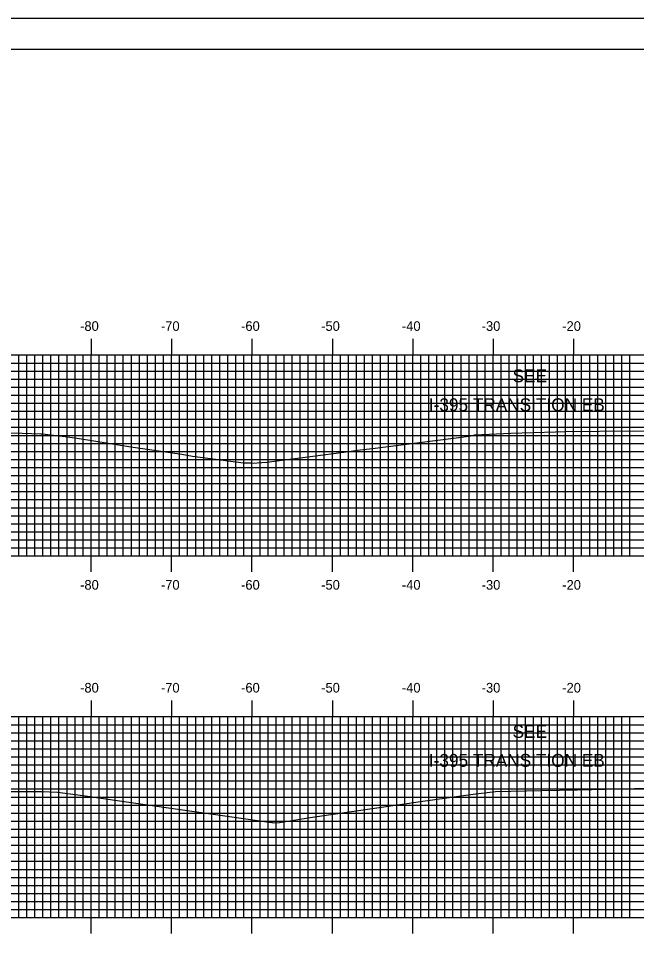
# Model space of a CAD drawing. Extents: x 842569 to 842912, y 363538 to 363758.
# Drawn here: x 842645.4 to 842722.2, y 363643.2 to 363757.6 of the extents above; entities that cross this region are included whole.
import ezdxf

# ---------------------------------------------------------------- set-up
doc = ezdxf.new("R2010")
doc.units = 0
for name, color, linetype in [('ANNOTATION', 7, 'Continuous'), ('BORDER', 7, 'Continuous'), ('H_V ANNOTATION', 7, 'Continuous'), ('M_Roadway_Centerline', 7, 'Continuous'), ('MAJOR', 7, 'Continuous'), ('MINOR', 7, 'Continuous'), ('PLOT BOUNDARY', 7, 'Continuous'), ('S_Roadway_Centerline', 7, 'Continuous')]:
    doc.layers.add(name, color=color, linetype=linetype)

msp = doc.modelspace()

# ---------------------------------------------------------------- linework, layer by layer
at = {"layer": 'BORDER'}
msp.add_lwpolyline([(842584.8, 363543.72), (842904.8, 363543.72), (842904.8, 363753.72), (842584.8, 363753.72)], close=True, dxfattribs=at)
at = {"layer": 'MAJOR'}
for p, q in [((842654.4, 363717.73), (842654.4, 363715.72)), ((842664.4, 363717.73), (842664.4, 363715.72)), ((842674.4, 363717.73), (842674.4, 363715.72)), ((842684.4, 363717.73), (842684.4, 363715.72)), ((842694.4, 363717.73), (842694.4, 363715.72)), ((842704.4, 363717.73), (842704.4, 363715.72)), ((842714.4, 363717.73), (842714.4, 363715.72)), ((842594.4, 363715.72), (842874.4, 363715.72)), ((842594.4, 363715.72), (842874.4, 363715.72)), ((842654.4, 363690.72), (842654.4, 363715.72)), ((842664.4, 363690.72), (842664.4, 363715.72)), ((842674.4, 363690.72), (842674.4, 363715.72)), ((842684.4, 363690.72), (842684.4, 363715.72)), ((842694.4, 363690.72), (842694.4, 363715.72)), ((842704.4, 363690.72), (842704.4, 363715.72)), ((842714.4, 363690.72), (842714.4, 363715.72)), ((842594.4, 363710.72), (842874.4, 363710.72)), ((842594.4, 363705.72), (842874.4, 363705.72)), ((842594.4, 363700.72), (842874.4, 363700.72)), ((842594.4, 363695.72), (842874.4, 363695.72)), ((842594.4, 363690.72), (842874.4, 363690.72)), ((842594.4, 363690.72), (842874.4, 363690.72)), ((842654.4, 363688.72), (842654.4, 363690.72)), ((842664.4, 363688.72), (842664.4, 363690.72)), ((842674.4, 363688.72), (842674.4, 363690.72)), ((842684.4, 363688.72), (842684.4, 363690.72)), ((842694.4, 363688.72), (842694.4, 363690.72)), ((842704.4, 363688.72), (842704.4, 363690.72)), ((842714.4, 363688.72), (842714.4, 363690.72)), ((842654.4, 363672.73), (842654.4, 363670.72)), ((842664.4, 363672.73), (842664.4, 363670.72)), ((842674.4, 363672.73), (842674.4, 363670.72)), ((842684.4, 363672.73), (842684.4, 363670.72)), ((842694.4, 363672.73), (842694.4, 363670.72)), ((842704.4, 363672.73), (842704.4, 363670.72)), ((842714.4, 363672.73), (842714.4, 363670.72)), ((842594.4, 363670.72), (842874.4, 363670.72)), ((842594.4, 363670.72), (842874.4, 363670.72)), ((842654.4, 363645.72), (842654.4, 363670.72)), ((842664.4, 363645.72), (842664.4, 363670.72)), ((842674.4, 363645.72), (842674.4, 363670.72)), ((842684.4, 363645.72), (842684.4, 363670.72)), ((842694.4, 363645.72), (842694.4, 363670.72)), ((842704.4, 363645.72), (842704.4, 363670.72)), ((842714.4, 363645.72), (842714.4, 363670.72)), ((842594.4, 363665.72), (842874.4, 363665.72)), ((842594.4, 363660.72), (842874.4, 363660.72)), ((842594.4, 363655.72), (842874.4, 363655.72)), ((842594.4, 363650.72), (842874.4, 363650.72)), ((842594.4, 363645.72), (842874.4, 363645.72)), ((842594.4, 363645.72), (842874.4, 363645.72)), ((842654.4, 363643.72), (842654.4, 363645.72)), ((842664.4, 363643.72), (842664.4, 363645.72)), ((842674.4, 363643.72), (842674.4, 363645.72)), ((842684.4, 363643.72), (842684.4, 363645.72)), ((842694.4, 363643.72), (842694.4, 363645.72)), ((842704.4, 363643.72), (842704.4, 363645.72)), ((842714.4, 363643.72), (842714.4, 363645.72))]:
    msp.add_line(p, q, dxfattribs=at)
at = {"layer": 'MINOR'}
for p, q in [((842645.4, 363690.72), (842645.4, 363715.72)), ((842646.4, 363690.72), (842646.4, 363715.72)), ((842647.4, 363690.72), (842647.4, 363715.72)), ((842648.4, 363690.72), (842648.4, 363715.72)), ((842649.4, 363690.72), (842649.4, 363715.72)), ((842650.4, 363690.72), (842650.4, 363715.72)), ((842651.4, 363690.72), (842651.4, 363715.72)), ((842652.4, 363690.72), (842652.4, 363715.72)), ((842653.4, 363690.72), (842653.4, 363715.72)), ((842655.4, 363690.72), (842655.4, 363715.72)), ((842656.4, 363690.72), (842656.4, 363715.72)), ((842657.4, 363690.72), (842657.4, 363715.72)), ((842658.4, 363690.72), (842658.4, 363715.72)), ((842659.4, 363690.72), (842659.4, 363715.72)), ((842660.4, 363690.72), (842660.4, 363715.72)), ((842661.4, 363690.72), (842661.4, 363715.72)), ((842662.4, 363690.72), (842662.4, 363715.72)), ((842663.4, 363690.72), (842663.4, 363715.72)), ((842665.4, 363690.72), (842665.4, 363715.72)), ((842666.4, 363690.72), (842666.4, 363715.72)), ((842667.4, 363690.72), (842667.4, 363715.72)), ((842668.4, 363690.72), (842668.4, 363715.72)), ((842669.4, 363690.72), (842669.4, 363715.72)), ((842670.4, 363690.72), (842670.4, 363715.72)), ((842671.4, 363690.72), (842671.4, 363715.72)), ((842672.4, 363690.72), (842672.4, 363715.72)), ((842673.4, 363690.72), (842673.4, 363715.72)), ((842675.4, 363690.72), (842675.4, 363715.72)), ((842676.4, 363690.72), (842676.4, 363715.72)), ((842677.4, 363690.72), (842677.4, 363715.72)), ((842678.4, 363690.72), (842678.4, 363715.72)), ((842679.4, 363690.72), (842679.4, 363715.72)), ((842680.4, 363690.72), (842680.4, 363715.72)), ((842681.4, 363690.72), (842681.4, 363715.72)), ((842682.4, 363690.72), (842682.4, 363715.72)), ((842683.4, 363690.72), (842683.4, 363715.72)), ((842685.4, 363690.72), (842685.4, 363715.72)), ((842686.4, 363690.72), (842686.4, 363715.72)), ((842687.4, 363690.72), (842687.4, 363715.72)), ((842688.4, 363690.72), (842688.4, 363715.72)), ((842689.4, 363690.72), (842689.4, 363715.72)), ((842690.4, 363690.72), (842690.4, 363715.72)), ((842691.4, 363690.72), (842691.4, 363715.72)), ((842692.4, 363690.72), (842692.4, 363715.72)), ((842693.4, 363690.72), (842693.4, 363715.72)), ((842695.4, 363690.72), (842695.4, 363715.72)), ((842696.4, 363690.72), (842696.4, 363715.72)), ((842697.4, 363690.72), (842697.4, 363715.72)), ((842698.4, 363690.72), (842698.4, 363715.72)), ((842699.4, 363690.72), (842699.4, 363715.72)), ((842700.4, 363690.72), (842700.4, 363715.72)), ((842701.4, 363690.72), (842701.4, 363715.72)), ((842702.4, 363690.72), (842702.4, 363715.72)), ((842703.4, 363690.72), (842703.4, 363715.72)), ((842705.4, 363690.72), (842705.4, 363715.72)), ((842706.4, 363690.72), (842706.4, 363715.72)), ((842707.4, 363690.72), (842707.4, 363715.72)), ((842708.4, 363690.72), (842708.4, 363715.72)), ((842709.4, 363690.72), (842709.4, 363715.72)), ((842710.4, 363690.72), (842710.4, 363715.72)), ((842711.4, 363690.72), (842711.4, 363715.72)), ((842712.4, 363690.72), (842712.4, 363715.72)), ((842713.4, 363690.72), (842713.4, 363715.72)), ((842715.4, 363690.72), (842715.4, 363715.72)), ((842716.4, 363690.72), (842716.4, 363715.72)), ((842717.4, 363690.72), (842717.4, 363715.72)), ((842718.4, 363690.72), (842718.4, 363715.72)), ((842719.4, 363690.72), (842719.4, 363715.72)), ((842720.4, 363690.72), (842720.4, 363715.72)), ((842721.4, 363690.72), (842721.4, 363715.72)), ((842594.4, 363714.72), (842874.4, 363714.72)), ((842594.4, 363713.72), (842874.4, 363713.72)), ((842594.4, 363712.72), (842874.4, 363712.72)), ((842594.4, 363711.72), (842874.4, 363711.72)), ((842594.4, 363709.72), (842874.4, 363709.72)), ((842594.4, 363708.72), (842874.4, 363708.72)), ((842594.4, 363707.72), (842874.4, 363707.72)), ((842594.4, 363706.72), (842874.4, 363706.72)), ((842594.4, 363704.72), (842874.4, 363704.72)), ((842594.4, 363703.72), (842874.4, 363703.72)), ((842594.4, 363702.72), (842874.4, 363702.72)), ((842594.4, 363701.72), (842874.4, 363701.72)), ((842594.4, 363699.72), (842874.4, 363699.72)), ((842594.4, 363698.72), (842874.4, 363698.72)), ((842594.4, 363697.72), (842874.4, 363697.72)), ((842594.4, 363696.72), (842874.4, 363696.72)), ((842594.4, 363694.72), (842874.4, 363694.72)), ((842594.4, 363693.72), (842874.4, 363693.72)), ((842594.4, 363692.72), (842874.4, 363692.72)), ((842594.4, 363691.72), (842874.4, 363691.72)), ((842645.4, 363645.72), (842645.4, 363670.72)), ((842646.4, 363645.72), (842646.4, 363670.72)), ((842647.4, 363645.72), (842647.4, 363670.72)), ((842648.4, 363645.72), (842648.4, 363670.72)), ((842649.4, 363645.72), (842649.4, 363670.72)), ((842650.4, 363645.72), (842650.4, 363670.72)), ((842651.4, 363645.72), (842651.4, 363670.72)), ((842652.4, 363645.72), (842652.4, 363670.72)), ((842653.4, 363645.72), (842653.4, 363670.72)), ((842655.4, 363645.72), (842655.4, 363670.72)), ((842656.4, 363645.72), (842656.4, 363670.72)), ((842657.4, 363645.72), (842657.4, 363670.72)), ((842658.4, 363645.72), (842658.4, 363670.72)), ((842659.4, 363645.72), (842659.4, 363670.72)), ((842660.4, 363645.72), (842660.4, 363670.72)), ((842661.4, 363645.72), (842661.4, 363670.72)), ((842662.4, 363645.72), (842662.4, 363670.72)), ((842663.4, 363645.72), (842663.4, 363670.72)), ((842665.4, 363645.72), (842665.4, 363670.72)), ((842666.4, 363645.72), (842666.4, 363670.72)), ((842667.4, 363645.72), (842667.4, 363670.72)), ((842668.4, 363645.72), (842668.4, 363670.72)), ((842669.4, 363645.72), (842669.4, 363670.72)), ((842670.4, 363645.72), (842670.4, 363670.72)), ((842671.4, 363645.72), (842671.4, 363670.72)), ((842672.4, 363645.72), (842672.4, 363670.72)), ((842673.4, 363645.72), (842673.4, 363670.72)), ((842675.4, 363645.72), (842675.4, 363670.72)), ((842676.4, 363645.72), (842676.4, 363670.72)), ((842677.4, 363645.72), (842677.4, 363670.72)), ((842678.4, 363645.72), (842678.4, 363670.72)), ((842679.4, 363645.72), (842679.4, 363670.72)), ((842680.4, 363645.72), (842680.4, 363670.72)), ((842681.4, 363645.72), (842681.4, 363670.72)), ((842682.4, 363645.72), (842682.4, 363670.72)), ((842683.4, 363645.72), (842683.4, 363670.72)), ((842685.4, 363645.72), (842685.4, 363670.72)), ((842686.4, 363645.72), (842686.4, 363670.72)), ((842687.4, 363645.72), (842687.4, 363670.72)), ((842688.4, 363645.72), (842688.4, 363670.72)), ((842689.4, 363645.72), (842689.4, 363670.72)), ((842690.4, 363645.72), (842690.4, 363670.72)), ((842691.4, 363645.72), (842691.4, 363670.72)), ((842692.4, 363645.72), (842692.4, 363670.72)), ((842693.4, 363645.72), (842693.4, 363670.72)), ((842695.4, 363645.72), (842695.4, 363670.72)), ((842696.4, 363645.72), (842696.4, 363670.72)), ((842697.4, 363645.72), (842697.4, 363670.72)), ((842698.4, 363645.72), (842698.4, 363670.72)), ((842699.4, 363645.72), (842699.4, 363670.72)), ((842700.4, 363645.72), (842700.4, 363670.72)), ((842701.4, 363645.72), (842701.4, 363670.72)), ((842702.4, 363645.72), (842702.4, 363670.72)), ((842703.4, 363645.72), (842703.4, 363670.72)), ((842705.4, 363645.72), (842705.4, 363670.72)), ((842706.4, 363645.72), (842706.4, 363670.72)), ((842707.4, 363645.72), (842707.4, 363670.72)), ((842708.4, 363645.72), (842708.4, 363670.72)), ((842709.4, 363645.72), (842709.4, 363670.72)), ((842710.4, 363645.72), (842710.4, 363670.72)), ((842711.4, 363645.72), (842711.4, 363670.72)), ((842712.4, 363645.72), (842712.4, 363670.72)), ((842713.4, 363645.72), (842713.4, 363670.72)), ((842715.4, 363645.72), (842715.4, 363670.72)), ((842716.4, 363645.72), (842716.4, 363670.72)), ((842717.4, 363645.72), (842717.4, 363670.72)), ((842718.4, 363645.72), (842718.4, 363670.72)), ((842719.4, 363645.72), (842719.4, 363670.72)), ((842720.4, 363645.72), (842720.4, 363670.72)), ((842721.4, 363645.72), (842721.4, 363670.72)), ((842594.4, 363669.72), (842874.4, 363669.72)), ((842594.4, 363668.72), (842874.4, 363668.72)), ((842594.4, 363667.72), (842874.4, 363667.72)), ((842594.4, 363666.72), (842874.4, 363666.72)), ((842594.4, 363664.72), (842874.4, 363664.72)), ((842594.4, 363663.72), (842874.4, 363663.72)), ((842594.4, 363662.72), (842874.4, 363662.72)), ((842594.4, 363661.72), (842874.4, 363661.72)), ((842594.4, 363659.72), (842874.4, 363659.72)), ((842594.4, 363658.72), (842874.4, 363658.72)), ((842594.4, 363657.72), (842874.4, 363657.72)), ((842594.4, 363656.72), (842874.4, 363656.72)), ((842594.4, 363654.72), (842874.4, 363654.72)), ((842594.4, 363653.72), (842874.4, 363653.72)), ((842594.4, 363652.72), (842874.4, 363652.72)), ((842594.4, 363651.72), (842874.4, 363651.72)), ((842594.4, 363649.72), (842874.4, 363649.72)), ((842594.4, 363648.72), (842874.4, 363648.72)), ((842594.4, 363647.72), (842874.4, 363647.72)), ((842594.4, 363646.72), (842874.4, 363646.72))]:
    msp.add_line(p, q, dxfattribs=at)
at = {"layer": 'PLOT BOUNDARY'}
msp.add_lwpolyline([(842568.61, 363537.6), (842908.61, 363537.6), (842908.61, 363757.6), (842568.61, 363757.6)], close=True, dxfattribs=at)
at = {"layer": 'S_Roadway_Centerline'}
for points in [[(842640.59, 363706.09), (842645.84, 363706), (842648.15, 363705.92), (842648.29, 363705.92), (842651.16, 363705.57), (842653.18, 363705.27), (842659.34, 363704.3), (842665.67, 363703.39), (842666.99, 363703.15), (842673.33, 363702.32), (842674.29, 363702.31), (842674.43, 363702.27), (842676.24, 363702.39), (842686.46, 363703.71), (842687.52, 363703.87), (842689.38, 363704.08), (842701.43, 363705.64), (842702.06, 363705.78), (842706.59, 363706), (842712.17, 363706.17), (842713.42, 363706.19), (842721.84, 363706.28), (842724.47, 363706.26)], [(842640.96, 363661.41), (842648.24, 363661.41), (842650.2, 363661.34), (842653.35, 363660.91), (842658.21, 363660.21), (842676.27, 363657.64), (842676.86, 363657.56), (842676.96, 363657.54), (842677.12, 363657.5), (842677.84, 363657.56), (842681.65, 363658.16), (842695.36, 363660.16), (842701.92, 363661.08), (842704.68, 363661.39), (842710.45, 363661.54), (842714.88, 363661.63), (842721.97, 363661.79), (842722.07, 363661.8), (842732.91, 363661.84)]]:
    msp.add_lwpolyline(points, dxfattribs=at)

# ---------------------------------------------------------------- texts
at = {"layer": 'ANNOTATION'}
for s, p in [('SEE', (842706.81, 363712.33)), ('I-395 TRANSITION EB', (842696.4, 363708.73)), ('SEE', (842706.81, 363668.08)), ('I-395 TRANSITION EB', (842696.4, 363664.48))]:
    msp.add_text(s, height=1.6, dxfattribs=at).set_placement(p)
at = {"layer": 'H_V ANNOTATION'}
for s, p in [('-80', (842653.03, 363718.72)), ('-70', (842663.08, 363718.72)), ('-60', (842673.05, 363718.72)), ('-50', (842683.01, 363718.72)), ('-40', (842693.05, 363718.72)), ('-30', (842702.97, 363718.72)), ('-20', (842712.99, 363718.72)), ('-80', (842653.03, 363686.52)), ('-70', (842663.08, 363686.52)), ('-60', (842673.05, 363686.52)), ('-50', (842683.01, 363686.52)), ('-40', (842693.05, 363686.52)), ('-30', (842702.97, 363686.52)), ('-20', (842712.99, 363686.52)), ('-80', (842653.03, 363673.72)), ('-70', (842663.08, 363673.72)), ('-60', (842673.05, 363673.72)), ('-50', (842683.01, 363673.72)), ('-40', (842693.05, 363673.72)), ('-30', (842702.97, 363673.72)), ('-20', (842712.99, 363673.72))]:
    msp.add_text(s, height=1.2, dxfattribs=at).set_placement(p)
at = {"layer": 'M_Roadway_Centerline'}
for s, p in [('C', (842721.83, 363706.28)), ('L', (842721.84, 363706.27)), ('C', (842722.06, 363661.8)), ('L', (842722.07, 363661.79))]:
    msp.add_text(s, height=0.0146, dxfattribs=at).set_placement(p)

doc.saveas('drawing.dxf')
